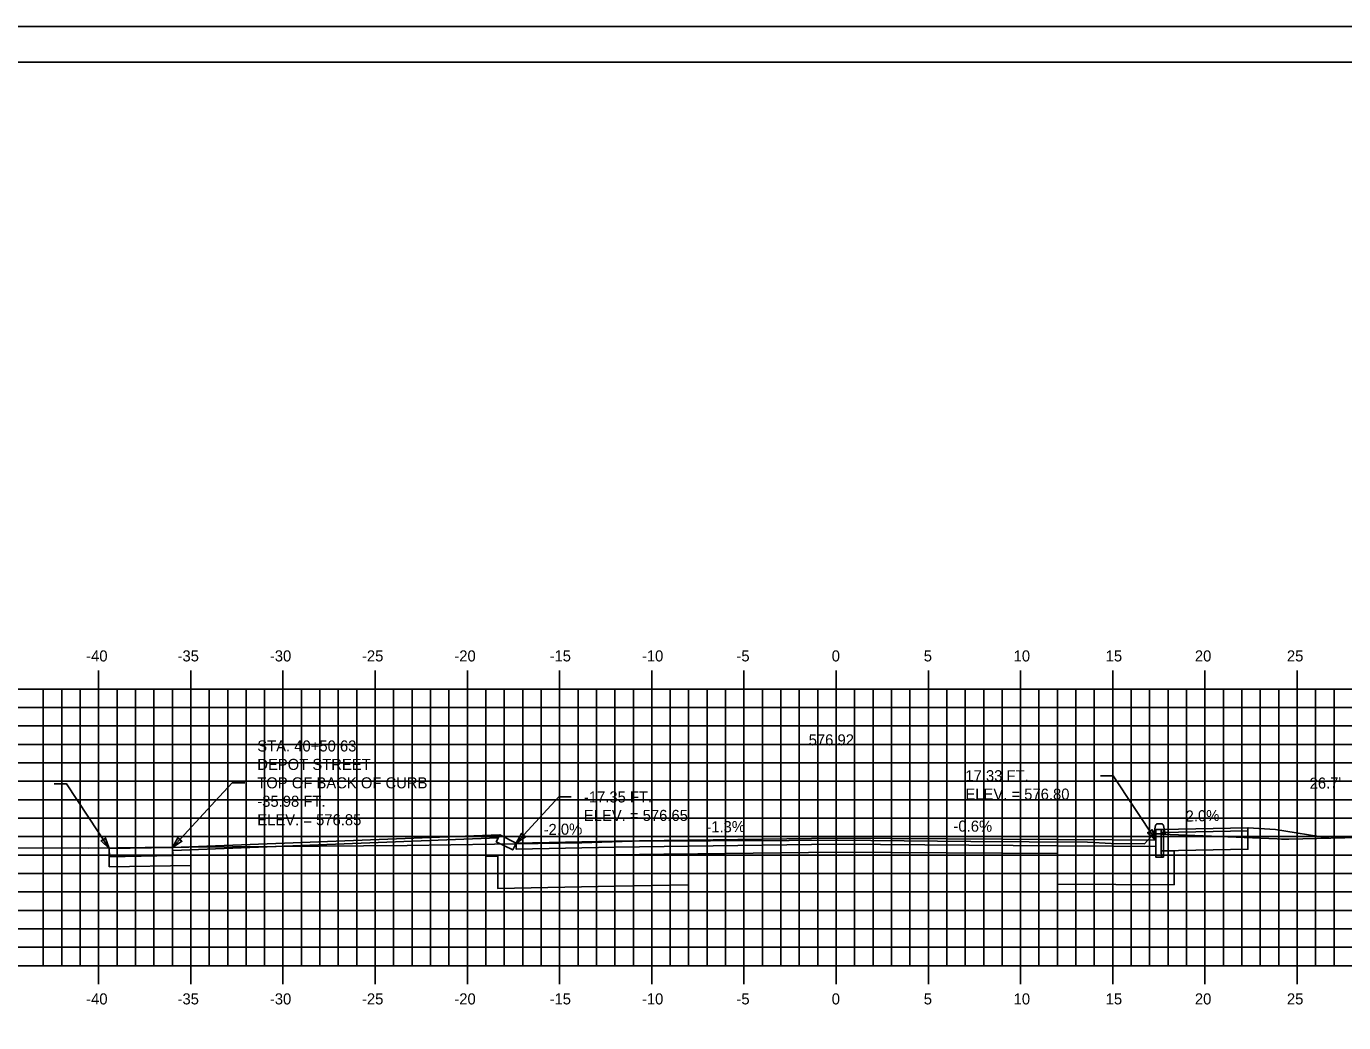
# Model space of a CAD drawing. Extents: x 1048565 to 1048735, y 781387 to 781497.
# Drawn here: x 1048604 to 1048675.4, y 781443.3 to 781497.3 of the extents above; entities that cross this region are included whole.
import ezdxf

# ---------------------------------------------------------------- set-up
doc = ezdxf.new("R2010")
doc.units = 0
for name, color, linetype in [('ANNOTATION', 7, 'Continuous'), ('BORDER', 7, 'Continuous'), ('D_Curb_Type1_Lt', 7, 'Continuous'), ('D_Curb_Type_5_Lt', 7, 'Continuous'), ('D_Roadway_Berm', 7, 'Continuous'), ('D_Roadway_Centerline', 7, 'Continuous'), ('D_Roadway_Centerline_Text', 7, 'Continuous'), ('D_Roadway_Edge_Shoulder', 7, 'Continuous'), ('D_Roadway_Edge_TW', 7, 'Continuous'), ('D_Roadway_Pavement', 7, 'Continuous'), ('D_Roadway_Sidewalks_Paved', 7, 'Continuous'), ('D_Roadway_SlopeLines', 7, 'Continuous'), ('D_Roadway_SubGrade', 7, 'Continuous'), ('D_Text_Standard', 7, 'Continuous'), ('H_V ANNOTATION', 7, 'Continuous'), ('MAJOR', 7, 'Continuous'), ('MINOR', 7, 'Continuous'), ('PLOT BOUNDARY', 7, 'Continuous'), ('S_Curb_Type_3', 7, 'Continuous'), ('S_Roadway_Centerline', 7, 'Continuous')]:
    doc.layers.add(name, color=color, linetype=linetype)

msp = doc.modelspace()

# ---------------------------------------------------------------- linework, layer by layer
at = {"layer": 'BORDER'}
msp.add_lwpolyline([(1048572.876, 781390.375), (1048732.876, 781390.375), (1048732.876, 781495.375), (1048572.876, 781495.375)], close=True, dxfattribs=at)
at = {"layer": 'D_Curb_Type1_Lt'}
msp.add_lwpolyline([(1048665.624, 781453.764), (1048665.624, 781452.264), (1048665.208, 781452.264), (1048665.208, 781453.764)], close=True, dxfattribs=at)
at = {"layer": 'D_Curb_Type_5_Lt'}
msp.add_lwpolyline([(1048629.632, 781453.474), (1048630.527, 781453.026), (1048630.34, 781452.654), (1048629.446, 781453.101)], close=True, dxfattribs=at)
at = {"layer": 'D_Roadway_Berm'}
msp.add_lwpolyline([(1048670.209, 781453.857), (1048671.709, 781453.767)], dxfattribs=at)
at = {"layer": 'D_Roadway_Edge_Shoulder'}
for points in [[(1048635.876, 781453.133), (1048630.527, 781453.026), (1048630.527, 781452.693), (1048635.876, 781452.8)], [(1048659.876, 781453.214), (1048662.876, 781453.194), (1048665.208, 781453.179), (1048665.208, 781452.846), (1048662.876, 781452.861), (1048659.876, 781452.88)]]:
    msp.add_lwpolyline(points, close=True, dxfattribs=at)
at = {"layer": 'D_Roadway_Edge_TW'}
msp.add_lwpolyline([(1048635.876, 781452.8), (1048635.876, 781453.133), (1048647.876, 781453.291), (1048659.876, 781453.214), (1048659.876, 781452.88), (1048647.876, 781452.958)], close=True, dxfattribs=at)
at = {"layer": 'D_Roadway_Pavement'}
msp.add_lwpolyline([(1048635.876, 781452.384), (1048635.876, 781452.8), (1048647.876, 781452.958), (1048659.876, 781452.88), (1048659.876, 781452.464), (1048647.876, 781452.541)], close=True, dxfattribs=at)
at = {"layer": 'D_Roadway_Sidewalks_Paved'}
msp.add_lwpolyline([(1048665.509, 781453.763), (1048670.209, 781453.857), (1048670.209, 781453.69), (1048665.509, 781453.596)], close=True, dxfattribs=at)
at = {"layer": 'D_Roadway_SlopeLines'}
msp.add_lwpolyline([(1048671.709, 781453.767), (1048674.604, 781453.284)], dxfattribs=at)
at = {"layer": 'D_Roadway_SubGrade'}
for p, q in [((1048629.632, 781453.474), (1048611.893, 781452.792)), ((1048629.632, 781453.474), (1048611.893, 781452.792)), ((1048629.55, 781453.309), (1048611.896, 781452.63)), ((1048608.457, 781452.735), (1048608.457, 781451.735)), ((1048659.876, 781450.797), (1048666.208, 781450.756))]:
    msp.add_line(p, q, dxfattribs=at)
for points in [[(1048665.509, 781453.596), (1048670.209, 781453.69), (1048670.209, 781452.69), (1048665.509, 781452.596)], [(1048608.457, 781452.735), (1048611.893, 781452.792), (1048611.9, 781452.345), (1048608.464, 781452.288)]]:
    msp.add_lwpolyline(points, close=True, dxfattribs=at)
for points in [[(1048629.527, 781452.309), (1048628.876, 781452.322), (1048628.876, 781453.283)], [(1048659.876, 781450.797), (1048659.876, 781452.88), (1048659.876, 781452.88), (1048662.876, 781452.861), (1048665.208, 781452.846), (1048665.208, 781452.263), (1048665.518, 781452.263), (1048665.509, 781452.596), (1048666.208, 781452.61), (1048666.208, 781450.756)], [(1048608.457, 781451.735), (1048612.876, 781451.808), (1048612.876, 781452.668)], [(1048630.527, 781452.693), (1048635.876, 781452.8), (1048635.876, 781452.384), (1048639.876, 781452.436), (1048639.876, 781450.769), (1048635.876, 781450.689), (1048629.527, 781450.562), (1048629.527, 781452.309)]]:
    msp.add_lwpolyline(points, dxfattribs=at)
at = {"layer": 'D_Text_Standard'}
for p, q in [((1048614.2, 781455.292), (1048615.122, 781456.292)), ((1048615.122, 781456.292), (1048615.802, 781456.292)), ((1048614.2, 781455.292), (1048611.893, 781452.792))]:
    msp.add_line(p, q, dxfattribs=at)
for points in [[(1048665.208, 781453.179), (1048662.89, 781456.679), (1048662.21, 781456.679)], [(1048608.457, 781452.734), (1048606.14, 781456.234), (1048605.46, 781456.234)], [(1048630.527, 781453.026), (1048632.833, 781455.526), (1048633.513, 781455.526)]]:
    msp.add_lwpolyline(points, dxfattribs=at)
for points in [[(1048665.208, 781453.179), (1048664.765, 781453.584), (1048665.008, 781453.745)], [(1048608.457, 781452.734), (1048608.015, 781453.139), (1048608.257, 781453.299)], [(1048611.893, 781452.792), (1048612.181, 781453.318), (1048612.395, 781453.121)], [(1048630.527, 781453.026), (1048630.814, 781453.553), (1048631.028, 781453.356)]]:
    msp.add_lwpolyline(points, close=True, dxfattribs=at)
at = {"layer": 'MAJOR'}
for p, q in [((1048607.876, 781462.377), (1048607.876, 781461.375)), ((1048612.876, 781462.377), (1048612.876, 781461.375)), ((1048617.876, 781462.377), (1048617.876, 781461.375)), ((1048622.876, 781462.377), (1048622.876, 781461.375)), ((1048627.876, 781462.377), (1048627.876, 781461.375)), ((1048632.876, 781462.377), (1048632.876, 781461.375)), ((1048637.876, 781462.377), (1048637.876, 781461.375)), ((1048642.876, 781462.377), (1048642.876, 781461.375)), ((1048647.876, 781462.377), (1048647.876, 781461.375)), ((1048652.876, 781462.377), (1048652.876, 781461.375)), ((1048657.876, 781462.377), (1048657.876, 781461.375)), ((1048662.876, 781462.377), (1048662.876, 781461.375)), ((1048667.876, 781462.377), (1048667.876, 781461.375)), ((1048672.876, 781462.377), (1048672.876, 781461.375)), ((1048577.876, 781461.375), (1048717.876, 781461.375)), ((1048577.876, 781461.375), (1048717.876, 781461.375)), ((1048607.876, 781446.375), (1048607.876, 781461.375)), ((1048612.876, 781446.375), (1048612.876, 781461.375)), ((1048617.876, 781446.375), (1048617.876, 781461.375)), ((1048622.876, 781446.375), (1048622.876, 781461.375)), ((1048627.876, 781446.375), (1048627.876, 781461.375)), ((1048632.876, 781446.375), (1048632.876, 781461.375)), ((1048637.876, 781446.375), (1048637.876, 781461.375)), ((1048642.876, 781446.375), (1048642.876, 781461.375)), ((1048647.876, 781446.375), (1048647.876, 781461.375)), ((1048652.876, 781446.375), (1048652.876, 781461.375)), ((1048657.876, 781446.375), (1048657.876, 781461.375)), ((1048662.876, 781446.375), (1048662.876, 781461.375)), ((1048667.876, 781446.375), (1048667.876, 781461.375)), ((1048672.876, 781446.375), (1048672.876, 781461.375)), ((1048577.876, 781456.375), (1048717.876, 781456.375)), ((1048577.876, 781451.375), (1048717.876, 781451.375)), ((1048577.876, 781446.375), (1048717.876, 781446.375)), ((1048577.876, 781446.375), (1048717.876, 781446.375)), ((1048607.876, 781445.373), (1048607.876, 781446.375)), ((1048612.876, 781445.373), (1048612.876, 781446.375)), ((1048617.876, 781445.373), (1048617.876, 781446.375)), ((1048622.876, 781445.373), (1048622.876, 781446.375)), ((1048627.876, 781445.373), (1048627.876, 781446.375)), ((1048632.876, 781445.373), (1048632.876, 781446.375)), ((1048637.876, 781445.373), (1048637.876, 781446.375)), ((1048642.876, 781445.373), (1048642.876, 781446.375)), ((1048647.876, 781445.373), (1048647.876, 781446.375)), ((1048652.876, 781445.373), (1048652.876, 781446.375)), ((1048657.876, 781445.373), (1048657.876, 781446.375)), ((1048662.876, 781445.373), (1048662.876, 781446.375)), ((1048667.876, 781445.373), (1048667.876, 781446.375)), ((1048672.876, 781445.373), (1048672.876, 781446.375))]:
    msp.add_line(p, q, dxfattribs=at)
at = {"layer": 'MINOR'}
for p, q in [((1048604.876, 781446.375), (1048604.876, 781461.375)), ((1048605.876, 781446.375), (1048605.876, 781461.375)), ((1048606.876, 781446.375), (1048606.876, 781461.375)), ((1048608.876, 781446.375), (1048608.876, 781461.375)), ((1048609.876, 781446.375), (1048609.876, 781461.375)), ((1048610.876, 781446.375), (1048610.876, 781461.375)), ((1048611.876, 781446.375), (1048611.876, 781461.375)), ((1048613.876, 781446.375), (1048613.876, 781461.375)), ((1048614.876, 781446.375), (1048614.876, 781461.375)), ((1048615.876, 781446.375), (1048615.876, 781461.375)), ((1048616.876, 781446.375), (1048616.876, 781461.375)), ((1048618.876, 781446.375), (1048618.876, 781461.375)), ((1048619.876, 781446.375), (1048619.876, 781461.375)), ((1048620.876, 781446.375), (1048620.876, 781461.375)), ((1048621.876, 781446.375), (1048621.876, 781461.375)), ((1048623.876, 781446.375), (1048623.876, 781461.375)), ((1048624.876, 781446.375), (1048624.876, 781461.375)), ((1048625.876, 781446.375), (1048625.876, 781461.375)), ((1048626.876, 781446.375), (1048626.876, 781461.375)), ((1048628.876, 781446.375), (1048628.876, 781461.375)), ((1048629.876, 781446.375), (1048629.876, 781461.375)), ((1048630.876, 781446.375), (1048630.876, 781461.375)), ((1048631.876, 781446.375), (1048631.876, 781461.375)), ((1048633.876, 781446.375), (1048633.876, 781461.375)), ((1048634.876, 781446.375), (1048634.876, 781461.375)), ((1048635.876, 781446.375), (1048635.876, 781461.375)), ((1048636.876, 781446.375), (1048636.876, 781461.375)), ((1048638.876, 781446.375), (1048638.876, 781461.375)), ((1048639.876, 781446.375), (1048639.876, 781461.375)), ((1048640.876, 781446.375), (1048640.876, 781461.375)), ((1048641.876, 781446.375), (1048641.876, 781461.375)), ((1048643.876, 781446.375), (1048643.876, 781461.375)), ((1048644.876, 781446.375), (1048644.876, 781461.375)), ((1048645.876, 781446.375), (1048645.876, 781461.375)), ((1048646.876, 781446.375), (1048646.876, 781461.375)), ((1048648.876, 781446.375), (1048648.876, 781461.375)), ((1048649.876, 781446.375), (1048649.876, 781461.375)), ((1048650.876, 781446.375), (1048650.876, 781461.375)), ((1048651.876, 781446.375), (1048651.876, 781461.375)), ((1048653.876, 781446.375), (1048653.876, 781461.375)), ((1048654.876, 781446.375), (1048654.876, 781461.375)), ((1048655.876, 781446.375), (1048655.876, 781461.375)), ((1048656.876, 781446.375), (1048656.876, 781461.375)), ((1048658.876, 781446.375), (1048658.876, 781461.375)), ((1048659.876, 781446.375), (1048659.876, 781461.375)), ((1048660.876, 781446.375), (1048660.876, 781461.375)), ((1048661.876, 781446.375), (1048661.876, 781461.375)), ((1048663.876, 781446.375), (1048663.876, 781461.375)), ((1048664.876, 781446.375), (1048664.876, 781461.375)), ((1048665.876, 781446.375), (1048665.876, 781461.375)), ((1048666.876, 781446.375), (1048666.876, 781461.375)), ((1048668.876, 781446.375), (1048668.876, 781461.375)), ((1048669.876, 781446.375), (1048669.876, 781461.375)), ((1048670.876, 781446.375), (1048670.876, 781461.375)), ((1048671.876, 781446.375), (1048671.876, 781461.375)), ((1048673.876, 781446.375), (1048673.876, 781461.375)), ((1048674.876, 781446.375), (1048674.876, 781461.375)), ((1048577.876, 781460.375), (1048717.876, 781460.375)), ((1048577.876, 781459.375), (1048717.876, 781459.375)), ((1048577.876, 781458.375), (1048717.876, 781458.375)), ((1048577.876, 781457.375), (1048717.876, 781457.375)), ((1048577.876, 781455.375), (1048717.876, 781455.375)), ((1048577.876, 781454.375), (1048717.876, 781454.375)), ((1048577.876, 781453.375), (1048717.876, 781453.375)), ((1048577.876, 781452.375), (1048717.876, 781452.375)), ((1048577.876, 781450.375), (1048717.876, 781450.375)), ((1048577.876, 781449.375), (1048717.876, 781449.375)), ((1048577.876, 781448.375), (1048717.876, 781448.375)), ((1048577.876, 781447.375), (1048717.876, 781447.375))]:
    msp.add_line(p, q, dxfattribs=at)
at = {"layer": 'PLOT BOUNDARY'}
msp.add_lwpolyline([(1048564.783, 781387.316), (1048734.783, 781387.316), (1048734.783, 781497.316), (1048564.783, 781497.316)], close=True, dxfattribs=at)
at = {"layer": 'S_Curb_Type_3'}
for points in [[(1048665.621, 781453.977), (1048665.724, 781453.532), (1048665.099, 781453.532), (1048665.201, 781453.977)], [(1048665.323, 781454.074), (1048665.499, 781454.074)]]:
    msp.add_lwpolyline(points, dxfattribs=at)
for centre, start, end in [((1048665.323, 781453.949), 90, 167.00538), ((1048665.499, 781453.949), 12.99462, 90)]:
    msp.add_arc(centre, 0.125, start, end, dxfattribs=at)
at = {"layer": 'S_Roadway_Centerline'}
msp.add_lwpolyline([(1048577.876, 781452.671), (1048603.257, 781452.774), (1048607.315, 781452.751), (1048610.395, 781452.794), (1048624.602, 781452.9), (1048634.077, 781453.042), (1048636.817, 781453.128), (1048645.312, 781453.163), (1048645.326, 781453.159), (1048647.876, 781453.174), (1048647.946, 781453.175), (1048655.173, 781453.111), (1048661.506, 781453.07), (1048662.781, 781453.011), (1048664.596, 781452.982), (1048664.962, 781453.374), (1048665.099, 781453.532), (1048671.794, 781453.251), (1048672.028, 781453.24), (1048672.094, 781453.239), (1048672.434, 781453.234), (1048679.244, 781453.391)], dxfattribs=at)

# ---------------------------------------------------------------- texts
at = {"layer": 'ANNOTATION'}
for s, rotation, p in [("26.7'", 0.7396, (1048673.557, 781455.97)), ('2.0%', 1.14576, (1048666.834, 781454.189)), ('-2.0%', 1.14576, (1048632.016, 781453.456)), ('-1.3%', 0.75383, (1048640.838, 781453.599)), ('-0.6%', 359.62927, (1048654.237, 781453.65))]:
    msp.add_text(s, height=0.6, rotation=rotation, dxfattribs=at).set_placement(p)
at = {"layer": 'D_Roadway_Centerline'}
for s, p in [('C', (1048647.871, 781453.291)), ('L', (1048647.876, 781453.284))]:
    msp.add_text(s, height=0.0146, dxfattribs=at).set_placement(p)
at = {"layer": 'D_Roadway_Centerline_Text'}
msp.add_text('576.92', height=0.6, dxfattribs=at).set_placement((1048646.386, 781458.323))
at = {"layer": 'D_Text_Standard'}
for s, p in [('STA. 40+50.63', (1048616.482, 781457.992)), ('DEPOT STREET', (1048616.482, 781456.992)), ('TOP OF BACK OF CURB', (1048616.482, 781455.992)), ('17.33 FT.', (1048654.885, 781456.379)), ('-17.35 FT.', (1048634.193, 781455.226)), ('ELEV. = 576.80', (1048654.885, 781455.379)), ('-35.98 FT.', (1048616.482, 781454.992)), ('ELEV. = 576.85', (1048616.482, 781453.992)), ('ELEV. = 576.65', (1048634.193, 781454.226))]:
    msp.add_text(s, height=0.6, dxfattribs=at).set_placement(p)
at = {"layer": 'H_V ANNOTATION'}
for s, p in [('-40', (1048607.202, 781462.875)), ('-35', (1048612.156, 781462.875)), ('-30', (1048617.164, 781462.875)), ('-25', (1048622.161, 781462.875)), ('-20', (1048627.169, 781462.875)), ('-15', (1048632.333, 781462.875)), ('-10', (1048637.341, 781462.875)), ('-5', (1048642.467, 781462.875)), ('0', (1048647.635, 781462.875)), ('5', (1048652.627, 781462.875)), ('10', (1048657.501, 781462.875)), ('15', (1048662.493, 781462.875)), ('20', (1048667.33, 781462.875)), ('25', (1048672.322, 781462.875)), ('-40', (1048607.202, 781444.275)), ('-35', (1048612.156, 781444.275)), ('-30', (1048617.164, 781444.275)), ('-25', (1048622.161, 781444.275)), ('-20', (1048627.169, 781444.275)), ('-15', (1048632.333, 781444.275)), ('-10', (1048637.341, 781444.275)), ('-5', (1048642.467, 781444.275)), ('0', (1048647.635, 781444.275)), ('5', (1048652.627, 781444.275)), ('10', (1048657.501, 781444.275)), ('15', (1048662.493, 781444.275)), ('20', (1048667.33, 781444.275)), ('25', (1048672.322, 781444.275))]:
    msp.add_text(s, height=0.6, dxfattribs=at).set_placement(p)
at = {"layer": 'S_Roadway_Centerline'}
for s, p in [('C', (1048647.87, 781453.174)), ('L', (1048647.876, 781453.166))]:
    msp.add_text(s, height=0.0146, dxfattribs=at).set_placement(p)

doc.saveas('drawing.dxf')
